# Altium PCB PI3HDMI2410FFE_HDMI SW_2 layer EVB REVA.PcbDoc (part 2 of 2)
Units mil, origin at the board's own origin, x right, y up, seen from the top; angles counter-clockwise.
Board outline 4919 x 3441 mil, 2 copper layers (Top Layer, Bottom Layer); 75 components, 82 nets, 1371 pads, 135 vias.
Unrouted connection lines stored in the file: 1.
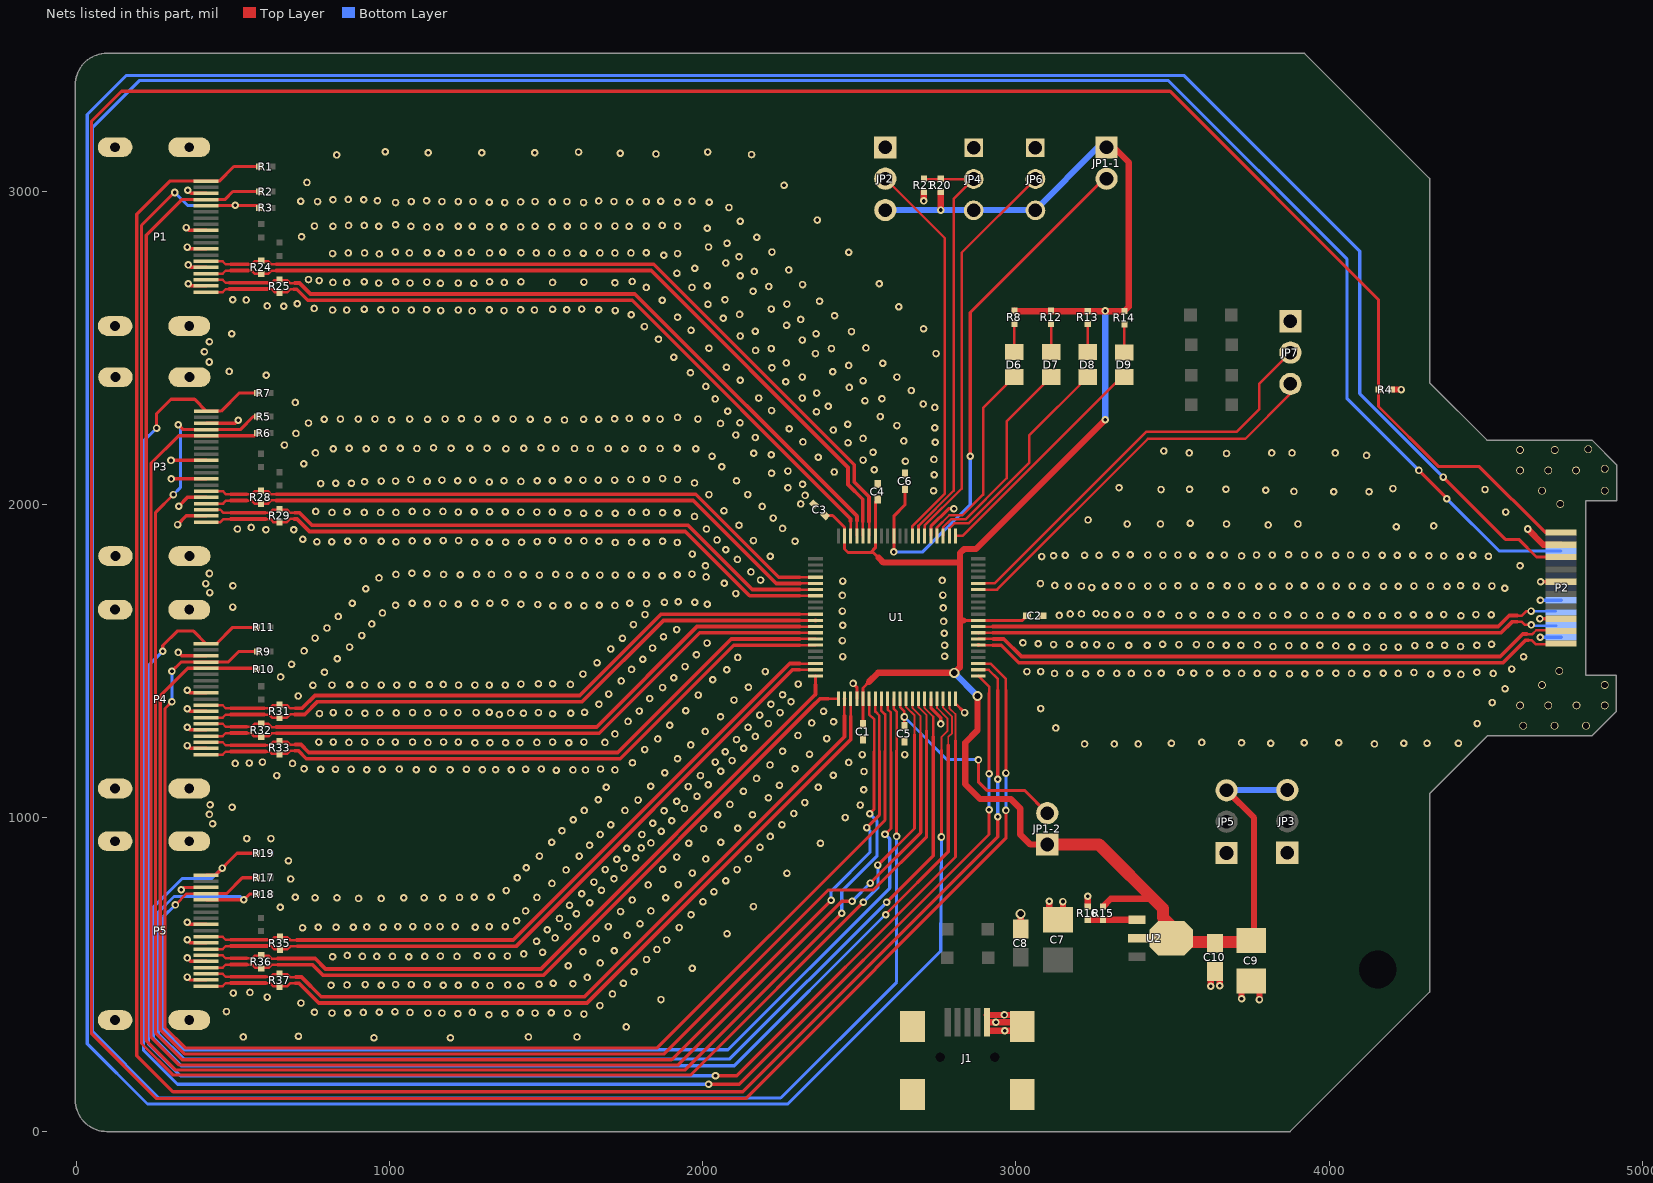
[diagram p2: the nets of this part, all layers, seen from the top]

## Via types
v1: diameter 24, hole 12, Top Layer to Bottom Layer, tented both sides, 131 vias
v2: diameter 32, hole 20, Top Layer to Bottom Layer, tented both sides, 4 vias

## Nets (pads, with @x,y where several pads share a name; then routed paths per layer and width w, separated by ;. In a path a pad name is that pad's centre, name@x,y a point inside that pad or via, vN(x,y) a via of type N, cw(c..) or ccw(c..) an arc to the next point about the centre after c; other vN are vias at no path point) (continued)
D1C+: P4.7 R31.2 U1.11 | length 2081.3
  Top Layer w8: P4.7@415.06,1320.11 468.32,1320.11 478,1329.8 495,1329.8 ; 600,1329.8 616.2,1329.8 625.68,1320.32 673.32,1320.32 683,1330 699,1330 ; 2309.65,1630 U1.11@2360,1630
  Top Layer w12: 495,1329.8 600,1329.8 ; 699,1330 730,1330 771,1371 1616,1371 1875,1630 2309.65,1630 ; U1.11@2360,1630.16 U1.11@2360.16,1630.16
D1C-: P4.9 R31.1 U1.10 | length 2081.5
  Top Layer w8: P4.9@415.06,1359.48 468.32,1359.48 478,1349.8 495,1349.8 ; 600,1349.8 618.8,1349.8 628.68,1359.68 673.32,1359.68 683,1350 700,1350 ; 2309.65,1650 2321.38,1650 2321.54,1649.84 U1.10@2360.16,1649.84
  Top Layer w12: 495,1349.8 600,1349.8 ; 700,1350 721.72,1350 762.72,1391 1607.72,1391 1866.72,1650 2309.65,1650
D1D+: P5.7 R35.2 U1.19 | length 2323.1
  Top Layer w8: P5.7@415.06,581.11 468.32,581.11 478,590.8 495,590.8 ; 610,590.8 622.2,590.8 632.68,580.32 674.32,580.32 684,590 706,590 ; 2310,1472.52 2310.16,1472.68 U1.19@2360.16,1472.68
  Top Layer w12: 495,590.8 610,590.8 ; 706,590 1404,590 2286.52,1472.52 2310,1472.52
D1D-: P5.9 R35.1 U1.18 | length 2322.4
  Top Layer w8: P5.9@415.06,620.48 468.32,620.48 478,610.8 495,610.8 ; 610,610.8 624.8,610.8 633.68,619.68 674.32,619.68 684,610 705,610 ; 2310,1492.52 2321.38,1492.52 2321.54,1492.36 U1.18@2360.16,1492.36
  Top Layer w12: 495,610.8 610,610.8 ; 705,610 1395.72,610 2278.24,1492.52 2310,1492.52
D2+: P2.4 U1.48 | length 1863.9
  Top Layer w8: U1.48@2880,1590.63 2927,1590.63 ; 4600,1625.63 4615,1625.63 4624.69,1615.94 v1(4644.69,1615.94)
  Top Layer w12: U1.48@2879.84,1590.79 U1.48@2880,1590.79 ; 2927,1590.63 4547.63,1590.63 4582.63,1625.63 4600,1625.63
  Bottom Layer w8: v1(4644.69,1615.94) 4647.63,1613 P2.4@4724,1613
D2-: P2.6 U1.49 | length 1862.7
  Top Layer w8: U1.49@2879.84,1610.47 2918.46,1610.47 2918.62,1610.63 2926,1610.63 ; 4600,1645.63 4615,1645.63 4629.37,1660 v1(4644,1660)
  Top Layer w12: 2926,1610.63 4539.35,1610.63 4574.35,1645.63 4600,1645.63
  Bottom Layer w8: v1(4644,1660) P2.6@4722,1660
D2A+: P1.4 R24.2 U1.76 | length 2559.8
  Top Layer w8: P1.4@415.06,2737.06 468.32,2737.06 478,2746.74 495,2746.74 ; 550,2746.74 560.26,2746.74 569.68,2737.32 614.32,2737.32 624,2747 640,2747 ; 2511.02,1946 2511.73,1945.29 U1.76@2511.73,1899.84
  Top Layer w12: 495,2746.74 550,2746.74 ; 640,2747 1835.72,2747 2464,2118.72 2464,2063.72 2511.02,2016.69 2511.02,1946
D2A-: P1.6 R24.1 U1.75 | length 2592.8
  Top Layer w8: P1.6@415.06,2776.43 468.32,2776.43 478,2766.74 495,2766.74 ; 550,2766.74 559.74,2766.74 569.68,2776.68 614.32,2776.68 624,2767 640,2767 ; U1.75@2531.02,1899.84 2531.02,1946
  Top Layer w12: 495,2766.74 550,2766.74 ; 640,2767 1844,2767 2484,2127 2484,2072 2531.02,2024.98 2531.02,1946
D2B+: P3.4 R28.2 U1.5 | length 2065.8
  Top Layer w8: P3.4@416.06,2003.06 469.32,2003.06 479,2012.74 495,2012.74 ; 545,2012.74 560.57,2012.74 570,2003.32 613.32,2003.32 623,2013 640,2013 ; 2311,1748.11 2321.38,1748.11 2321.54,1748.27 U1.5@2360.16,1748.27
  Top Layer w12: 495,2012.74 545,2012.74 ; 640,2013 1969.72,2013 2234.61,1748.11 2311,1748.11
D2B-: P3.6 R28.1 U1.4 | length 2066
  Top Layer w8: P3.6@416.06,2042.43 469.32,2042.43 479,2032.74 495,2032.74 ; 545,2032.74 561.74,2032.74 571.68,2042.68 613.32,2042.68 623,2033 640,2033 ; 2310,1768.11 2360,1768.11 U1.4@2360.16,1767.95
  Top Layer w12: 495,2032.74 545,2032.74 ; 640,2033 1978,2033 2242.89,1768.11 2310,1768.11
D2C+: P4.4 R32.2 U1.13 | length 2090.3
  Top Layer w8: P4.4@415.06,1261.06 468.32,1261.06 478,1270.74 495,1270.74 ; 545,1270.74 558.26,1270.74 568.68,1260.32 614.32,1260.32 624,1270 640,1270 ; 2310,1590.63 2360,1590.63 U1.13@2360.16,1590.79
  Top Layer w12: 495,1270.74 545,1270.74 ; 640,1270 1670,1270 1990.63,1590.63 2310,1590.63
D2C-: P4.6 R32.1 U1.12 | length 2089.7
  Top Layer w8: P4.6@415.06,1300.43 468.32,1300.43 478,1290.74 495,1290.74 ; 544,1290.74 560.74,1290.74 569.68,1299.68 614.32,1299.68 624,1290 640,1290 ; 2310,1610.63 2321.38,1610.63 2321.54,1610.47 U1.12@2360.16,1610.47
  Top Layer w12: 495,1290.74 544,1290.74 ; 640,1290 1661.72,1290 1982.35,1610.63 2310,1610.63
D2D+: P5.4 R36.2 U1.21 | length 2409.3
  Top Layer w8: P5.4@415.06,522.06 468.32,522.06 478,531.74 495,531.74 ; 545,531.74 562.26,531.74 572.68,521.32 614.32,521.32 624,531 645,531 ; 2400,1380.16 U1.21@2432.99,1380.16
  Top Layer w12: 495,531.74 545,531.74 ; 645,531 755,531 788,498 1492,498 2360.62,1366.62 2360.76,1366.62 2374.3,1380.16 2400,1380.16
D2D-: P5.6 R36.1 U1.20 | length 2392.2
  Top Layer w8: P5.6@415.06,561.43 468.32,561.43 478,551.74 495,551.74 ; 544,551.74 561.74,551.74 570.68,560.68 614.32,560.68 624,551 645,551 ; 2360.16,1425 U1.20@2360.16,1452.99
  Top Layer w12: 495,551.74 544,551.74 ; 645,551 763.28,551 796.28,518 1483.72,518 2352.34,1386.62 2352.48,1386.62 2360.16,1394.3 2360.16,1425
D3+: P2.1 U1.46 | length 1894.3
  Top Layer w8: U1.46@2880,1551.26 2926,1551.26 ; 4634,1566.57 4646.57,1566.57 4659.15,1554 P2.1@4716,1554
  Top Layer w12: U1.46@2879.84,1551.42 U1.46@2880,1551.42 ; 2926,1551.26 2952.74,1551.26 3009,1495 4554,1495 4625.57,1566.57 4634,1566.57
D3-: P2.3 U1.47 | length 1893.3
  Top Layer w8: U1.47@2879.84,1571.1 2918.46,1571.1 2918.62,1571.26 2928,1571.26 ; 4630,1586.57 4648,1586.57 4660.43,1599 P2.3@4715,1599
  Top Layer w12: 2928,1571.26 2961.02,1571.26 3017.28,1515 4545.72,1515 4617.29,1586.57 4630,1586.57
D3A+: P1.1 R25.2 U1.78 | length 2427.8
  Top Layer w8: P1.1@415.06,2678 468.32,2678 478,2687.68 489,2687.68 ; 615,2687.68 625.32,2687.68 635.68,2677.32 673.32,2677.32 683,2687 695,2687 ; 2472.2,1947 2472.2,1938.62 2472.36,1938.46 U1.78@2472.36,1899.84
  Top Layer w12: 489,2687.68 615,2687.68 ; 695,2687 704.72,2687 739.72,2652 1775,2652 2472.2,1954.8 2472.2,1947
D3A-: P1.3 R25.1 U1.77 | length 2460.3
  Top Layer w8: P1.3@415.06,2717.37 468.32,2717.37 478,2707.69 490,2707.69 ; 615,2707.69 624.69,2707.69 633.68,2716.68 673.32,2716.68 683,2707 698,2707 ; U1.77@2492.05,1899.84 2492.2,1900 2492.2,1948
  Top Layer w12: 490,2707.69 615,2707.69 ; 698,2707 713,2707 748,2672 1783.28,2672 2492.2,1963.08 2492.2,1948
D3B+: P3.1 R29.2 U1.7 | length 2057.7
  Top Layer w8: P3.1@416.06,1944 461,1944 470.68,1953.68 495,1953.68 ; 605,1953.68 620.63,1953.68 630,1944.32 673.32,1944.32 683,1954 697,1954 ; 2310,1708.74 2321.38,1708.74 2321.54,1708.9 U1.7@2360.16,1708.9
  Top Layer w12: 495,1953.68 605,1953.68 ; 697,1954 705,1954 745,1914 1944.72,1914 2149.98,1708.74 2310,1708.74
D3B-: P3.3 R29.1 U1.6 | length 2057.9
  Top Layer w8: P3.3@416.06,1983.37 461,1983.37 470.68,1973.69 495,1973.69 ; 604,1973.69 618.69,1973.69 628.68,1983.68 673.32,1983.68 683,1974 699,1974 ; 2310,1728.74 2360,1728.74 U1.6@2360.16,1728.58
  Top Layer w12: 495,1973.69 604,1973.69 ; 699,1974 713.28,1974 753.28,1934 1953,1934 2158.26,1728.74 2310,1728.74
D3C+: P4.1 R33.2 U1.15 | length 2116.6
  Top Layer w8: P4.1@415.06,1202 468.32,1202 478,1211.68 495,1211.68 ; 605,1211.68 618.32,1211.68 625.68,1204.32 673.32,1204.32 683,1214 699,1214 ; 2310,1551.26 2360,1551.26 U1.15@2360.16,1551.42
  Top Layer w12: 495,1211.68 605,1211.68 ; 699,1214 709.72,1214 734.72,1189 1737,1189 2099.26,1551.26 2310,1551.26
D3C-: P4.3 R33.1 U1.14 | length 2118.6
  Top Layer w8: P4.3@415.06,1241.37 468.32,1241.37 478,1231.69 495,1231.69 ; 603,1231.69 617.69,1231.69 629.68,1243.68 673.32,1243.68 683,1234 700,1234 ; 2309,1571.26 2321.38,1571.26 2321.54,1571.1 U1.14@2360.16,1571.1
  Top Layer w12: 495,1231.69 603,1231.69 ; 700,1234 718,1234 743,1209 1728.72,1209 2090.98,1571.26 2309,1571.26
D3D+: P5.1 R37.2 U1.23 | length 2574.1
  Top Layer w8: P5.1@415.06,463 468.32,463 478,472.68 495,472.68 ; 605,472.68 619.32,472.68 629.68,462.32 673.32,462.32 683,472 700,472 ; 2472.36,1323.53 U1.23@2472.36,1380.16
  Top Layer w12: 495,472.68 605,472.68 ; 700,472 711.72,472 774.72,409 1631,409 2472.52,1250.52 2472.52,1323.53
D3D-: P5.3 R37.1 U1.22 | length 2540.4
  Top Layer w8: P5.3@415.06,502.37 468.32,502.37 478,492.69 495,492.69 ; 605,492.69 620.69,492.69 629.68,501.68 673.32,501.68 683,492 701,492 ; 2452.52,1326.33 U1.22@2452.52,1380
  Top Layer w12: 495,492.69 605,492.69 ; 701,492 720,492 783,429 1622.72,429 2452.52,1258.8 2452.52,1326.33 ; U1.22@2452.68,1380 U1.22@2452.68,1380.16
GND: C1.2 C2.2 C3.2 C4.2 C5.2 C6.2 C7.2 C8.1 C9.2 C10.1 J1.5 JP2.1 JP3.1 JP4.1 JP5.1 JP6.1 JP7.1 P1.2 P1.5 P1.8 P1.11 P1.17 P1.20 P1.21 P1.22 P1.23 P2.2 P2.5 P2.8 P2.11 P2.17 P2.20 P3.2 P3.5 P3.8 P3.11 P3.17 P3.20 P3.21 P3.22 P3.23 P4.2 P4.5 P4.8 P4.11 P4.17 P4.20 P4.21 P4.22 P4.23 P5.2 P5.5 P5.8 P5.11 P5.17 P5.20 P5.21 P5.22 P5.23 pad.6 pad.7 pad.9 pad.10 pad.11 pad.12 pad.13 pad.14 pad.15 pad.16 pad.17 pad.18 pad.19 pad.20 pad.21 pad.22 pad.23 pad.24 pad.25 pad.26 pad.27 pad.28 pad.29 pad.30 pad.31 pad.32 pad.33 pad.34 pad.35 pad.36 pad.37 pad.38 pad.39 pad.40 pad.41 pad.42 pad.43 pad.44 pad.45 pad.46 pad.47 pad.48 pad.49 pad.50 pad.51 pad.52 pad.53 pad.54 pad.55 pad.56 pad.57 pad.58 pad.59 pad.60 pad.61 pad.62 pad.63 pad.64 pad.65 pad.66 pad.67 pad.68 pad.69 pad.70 pad.71 pad.72 pad.73 pad.74 pad.75 pad.76 pad.77 pad.78 pad.79 pad.80 pad.81 pad.82 pad.83 pad.84 pad.85 pad.86 pad.87 pad.88 pad.89 pad.90 pad.91 pad.92 pad.93 pad.94 pad.95 pad.96 pad.97 pad.98 pad.99 pad.100 pad.101 pad.102 pad.103 pad.104 pad.105 pad.106 pad.107 pad.108 pad.109 pad.110 pad.111 pad.112 pad.113 pad.114 pad.115 pad.116 pad.117 pad.118 pad.119 pad.120 pad.121 pad.122 pad.123 pad.124 pad.125 pad.126 pad.127 pad.128 pad.129 pad.132 pad.133 pad.134 pad.135 pad.136 pad.137 pad.138 pad.139 pad.140 pad.141 pad.142 pad.144 pad.145 pad.146 pad.147 pad.149 pad.150 pad.151 pad.152 pad.153 pad.154 pad.155 pad.156 pad.157 pad.158 pad.159 pad.160 pad.161 pad.162 pad.163 pad.164 pad.165 pad.166 pad.167 pad.168 pad.169 pad.170 pad.171 pad.172 pad.173 pad.174 pad.175 pad.176 pad.177 pad.178 pad.179 pad.180 pad.181 pad.182 pad.183 pad.184 pad.185 pad.186 pad.187 pad.188 pad.189 pad.190 pad.191 pad.192 pad.193 pad.194 pad.195 pad.196 pad.197 pad.198 pad.199 pad.200 pad.201 pad.202 pad.203 pad.204 pad.205 pad.206 pad.207 pad.208 pad.209 pad.210 pad.211 pad.212 pad.213 pad.214 pad.215 pad.216 pad.217 pad.218 pad.219 pad.220 pad.221 pad.222 pad.223 pad.224 pad.225 pad.226 pad.227 pad.228 pad.229 pad.230 pad.231 pad.232 pad.233 pad.234 pad.235 pad.236 pad.237 pad.238 pad.239 pad.240 pad.241 pad.242 pad.243 pad.244 pad.245 pad.246 pad.247 pad.248 pad.249 pad.250 pad.251 pad.252 pad.253 pad.254 pad.255 pad.256 pad.257 pad.258 pad.259 pad.260 pad.261 pad.262 pad.263 pad.264 pad.265 pad.266 pad.267 pad.268 pad.269 pad.270 pad.271 pad.272 pad.273 pad.274 pad.275 pad.276 pad.277 pad.278 pad.279 pad.280 pad.281 pad.282 pad.283 pad.284 pad.285 pad.286 pad.287 pad.288 pad.289 pad.290 pad.291 pad.292 pad.293 pad.294 pad.295 pad.296 pad.297 pad.298 pad.299 pad.300 pad.301 pad.302 pad.303 pad.304 pad.305 pad.306 pad.307 pad.308 pad.309 pad.310 pad.311 pad.312 pad.313 pad.314 pad.315 pad.316 pad.317 pad.318 pad.319 pad.320 pad.321 pad.322 pad.323 pad.324 pad.325 pad.326 pad.327 pad.328 pad.329 pad.330 pad.331 pad.332 pad.333 pad.334 pad.335 pad.336 pad.337 pad.338 pad.339 pad.340 pad.341 pad.342 pad.343 pad.344 pad.345 pad.346 pad.347 pad.348 pad.349 pad.350 pad.351 pad.352 pad.353 pad.354 pad.355 pad.356 pad.357 pad.358 pad.359 pad.360 pad.361 pad.362 pad.363 pad.364 pad.365 pad.366 pad.367 pad.368 pad.369 pad.370 pad.371 pad.372 pad.373 pad.374 pad.375 pad.376 pad.377 pad.378 pad.379 pad.380 pad.381 pad.382 pad.383 pad.384 pad.385 pad.386 pad.387 pad.388 pad.389 pad.390 pad.391 pad.392 pad.393 pad.394 pad.395 pad.396 pad.397 pad.398 pad.399 pad.400 pad.401 pad.402 pad.403 pad.404 pad.405 pad.406 pad.407 pad.408 pad.409 pad.410 pad.411 pad.412 pad.413 pad.414 pad.415 pad.416 pad.417 pad.418 pad.419 pad.420 pad.421 pad.422 pad.423 pad.424 pad.425 pad.426 pad.427 pad.428 pad.429 pad.430 pad.431 pad.432 pad.433 pad.434 pad.435 pad.436 pad.437 pad.438 pad.439 pad.440 pad.441 pad.442 pad.443 pad.444 pad.445 pad.446 pad.447 pad.448 pad.449 pad.450 pad.451 pad.452 pad.453 pad.454 pad.455 pad.456 pad.457 pad.458 pad.459 pad.460 pad.461 pad.462 pad.463 pad.464 pad.465 pad.466 pad.467 pad.468 pad.469 pad.470 pad.471 pad.472 pad.473 pad.474 pad.475 pad.476 pad.477 pad.478 pad.479 pad.480 pad.481 pad.482 pad.483 pad.484 pad.485 pad.486 pad.487 pad.488 pad.489 pad.490 pad.491 pad.492 pad.493 pad.494 pad.495 pad.496 pad.497 pad.498 pad.499 pad.500 pad.501 pad.516 pad.550 pad.566 pad.571 pad.577 pad.592 pad.593 pad.594 pad.595 pad.596 pad.597 pad.598 pad.599 pad.600 pad.601 pad.602 pad.603 pad.604 pad.605 pad.606 pad.607 pad.608 pad.610 pad.611 pad.612 pad.613 pad.614 pad.615 pad.616 pad.617 pad.618 pad.619 pad.620 pad.621 pad.622 pad.623 pad.624 pad.629 pad.630 pad.631 pad.632 pad.633 pad.634 pad.635 pad.636 pad.637 pad.638 pad.639 pad.640 pad.641 pad.642 pad.643 pad.644 pad.645 pad.646 pad.647 pad.648 pad.649 pad.650 pad.651 pad.652 pad.653 pad.654 pad.655 pad.656 pad.657 pad.658 pad.659 pad.660 pad.661 pad.662 pad.663 pad.664 pad.665 pad.666 pad.667 pad.668 pad.669 pad.670 pad.671 pad.672 pad.673 pad.674 pad.675 pad.676 pad.677 pad.678 pad.679 pad.680 pad.681 pad.682 pad.683 pad.684 pad.685 pad.686 pad.687 pad.688 pad.689 pad.690 pad.691 pad.692 pad.693 pad.694 pad.695 pad.696 pad.697 pad.698 pad.699 pad.700 pad.701 pad.702 pad.703 pad.704 pad.705 pad.706 pad.707 pad.708 pad.709 pad.710 pad.711 pad.712 pad.713 pad.714 pad.715 pad.716 pad.717 pad.718 pad.719 pad.720 pad.721 pad.722 pad.723 pad.724 pad.725 pad.726 pad.727 pad.728 pad.729 pad.730 pad.731 pad.732 pad.733 pad.734 pad.735 pad.736 pad.737 pad.738 pad.739 pad.740 pad.741 pad.742 pad.743 pad.744 pad.745 pad.746 pad.747 pad.748 pad.749 pad.750 pad.751 pad.752 pad.753 pad.754 pad.755 pad.756 pad.757 pad.758 pad.759 pad.760 pad.761 pad.762 pad.763 pad.764 pad.765 pad.766 pad.767 pad.768 pad.769 pad.770 pad.771 pad.772 pad.773 pad.774 pad.775 pad.776 pad.777 pad.778 pad.779 pad.780 pad.781 pad.782 pad.783 pad.784 pad.785 pad.786 pad.787 pad.788 pad.789 pad.790 pad.791 pad.792 pad.793 pad.794 pad.795 pad.796 pad.797 pad.798 pad.799 pad.800 pad.801 pad.802 pad.803 pad.804 pad.805 pad.806 pad.807 pad.808 pad.809 pad.810 pad.811 pad.812 pad.813 pad.814 pad.815 pad.816 pad.817 pad.818 pad.819 pad.820 pad.823 pad.824 pad.825 pad.826 pad.827 pad.828 pad.829 pad.830 pad.831 pad.832 pad.833 pad.834 pad.835 pad.836 pad.837 pad.838 pad.839 pad.840 pad.841 pad.842 pad.843 pad.844 pad.845 pad.846 pad.847 pad.848 pad.849 pad.850 pad.851 pad.852 pad.853 pad.854 pad.856 pad.857 pad.858 pad.859 pad.860 pad.861 pad.862 pad.863 pad.864 pad.865 pad.866 pad.867 pad.868 pad.869 pad.870 pad.871 pad.872 pad.873 pad.874 pad.875 pad.876 pad.877 pad.878 pad.879 pad.880 pad.881 pad.882 pad.883 pad.884 pad.885 pad.886 pad.887 pad.888 pad.889 pad.890 pad.891 pad.892 pad.893 pad.894 pad.895 pad.896 pad.897 pad.898 pad.899 pad.900 pad.901 pad.902 pad.903 pad.904 pad.905 pad.906 pad.907 pad.908 pad.909 pad.910 pad.911 pad.912 pad.913 pad.914 pad.915 pad.916 pad.917 pad.918 pad.919 pad.920 pad.921 pad.922 pad.923 pad.924 pad.925 pad.926 pad.927 pad.928 pad.929 pad.930 pad.931 pad.932 pad.933 pad.934 pad.935 pad.936 pad.937 pad.938 pad.939 pad.940 pad.941 pad.942 pad.943 pad.944 pad.945 pad.946 pad.947 pad.948 pad.949 pad.950 pad.951 pad.952 pad.953 pad.954 pad.955 pad.956 pad.957 pad.958 pad.959 pad.960 pad.961 pad.962 pad.963 pad.964 pad.965 pad.966 pad.967 pad.968 pad.969 pad.970 pad.971 pad.972 pad.973 pad.974 pad.975 pad.976 pad.977 pad.978 pad.979 pad.980 pad.981 pad.982 pad.983 pad.984 pad.985 pad.986 pad.987 pad.988 pad.989 pad.990 pad.991 pad.992 pad.993 pad.994 pad.995 pad.996 pad.997 pad.998 pad.999 pad.1000 pad.1001 pad.1002 pad.1003 pad.1006 pad.1007 pad.1008 pad.1009 pad.1010 pad.1011 pad.1012 pad.1013 pad.1014 pad.1015 pad.1016 pad.1017 pad.1018 pad.1019 pad.1020 pad.1021 pad.1022 pad.1023 pad.1024 pad.1025 pad.1026 pad.1027 pad.1028 pad.1029 pad.1030 pad.1031 pad.1032 pad.1033 pad.1034 pad.1035 pad.1036 pad.1037 pad.1038 pad.1039 pad.1041 pad.1042 pad.1043 pad.1044 pad.1046 pad.1047 pad.1048 pad.1049 pad.1050 pad.1051 pad.1052 pad.1053 pad.1054 pad.1055 pad.1056 pad.1057 pad.1058 pad.1059 pad.1060 pad.1062 pad.1063 pad.1065 pad.1066 pad.1069 pad.1070 pad.1072 pad.1074 pad.1076 pad.1079 pad.1082 pad.1085 pad.1088 pad.1090 pad.1092 pad.1094 pad.1097 pad.1098 pad.1099 pad.1101 pad.1104 pad.1107 pad.1110 pad.1112 pad.1115 pad.1117 pad.1119 pad.1121 pad.1123 pad.1125 pad.1127 pad.1129 pad.1131 pad.1132 pad.1133 pad.1134 pad.1135 pad.1136 pad.1137 R4.1 R16.2 R21.2 U1.24 U1.36 U1.40 U1.65 | length 2877.3
  Top Layer w10: v1(336,771) 342.96,777.96 P5.17@415.06,777.96 ; v1(2480,1429) 2492.05,1416.95 U1.24@2492.05,1380.16 ; U1.36@2728.27,1380.16 2728.27,1351.73 2760,1320 v1(2760,1300) ; U1.65@2728.27,1899.84 2728.27,1930.27 2785,1987 v1(2802,1987) ; U1.40@2807.01,1380.16 2807.01,1364.99 v1(2836,1336)
  Top Layer w11: v1(303.15,2140.85) P3.11@416.06,2140.85 ; v1(304.2,2081.8) P3.8@416.06,2081.8 ; v1(324,1936) 351.68,1963.68 P3.2@416.06,1963.68 ; v1(326,1528) 337.04,1516.96 P4.17@415.06,1516.96 ; v1(328,1995) 355.74,2022.74 P3.5@416.06,2022.74 ; v1(352,2884) 361.15,2874.85 P1.11@415.06,2874.85 ; v1(355,492) 364.32,482.68 P5.2@415.06,482.68 ; v1(355,553) 366.26,541.74 P5.5@415.06,541.74 ; v1(355,611) 365.2,600.8 P5.8@415.06,600.8 ; v1(355,667) 362.15,659.85 P5.11@415.06,659.85 ; v1(355,1231) 364.32,1221.68 P4.2@415.06,1221.68 ; v1(355,1289) 363.26,1280.74 P4.5@415.06,1280.74 ; v1(355,1348) 363.2,1339.8 P4.8@415.06,1339.8 ; v1(355,1407) 363.15,1398.85 P4.11@415.06,1398.85 ; v1(355,2822) 361.2,2815.8 P1.8@415.06,2815.8 ; v1(357,3003) 367.04,2992.96 P1.17@415.06,2992.96 ; v1(358,2705) 365.32,2697.68 P1.2@415.06,2697.68 ; v1(358,2765) 366.26,2756.74 P1.5@415.06,2756.74 ; P3.17@416.06,2258.96 507.96,2258.96 v1(518,2269)
  Top Layer w12: v1(4672.37,1635.63) P2.5@4739.63,1635.63 ; v1(4674.26,1753.74) P2.11@4739.63,1753.74
  Top Layer w20: v1(2706,2969) R21.2@2706,2998 ; J1.5@2907,371 J1.5@2998,371 ; J1.5@2908,321 J1.5@2999,321 ; J1.5@2907.99,347.9 J1.5@2991.1,347.9 ; C8.1@3015,645 v2(3015,694) ; C7.2@3106,691 v1(3106,734) ; C7.2@3150,683 v1(3150,733) ; R16.2@3229.03,717.27 v1(3229.03,749.97) ; v1(3622,463) C10.1@3622,495 ; v1(3650,464) C10.1@3650,493 ; v1(3720,423) C9.2@3720,454 ; v1(3777,420) C9.2@3777,450 ; R4.1@4199.95,2367.03 v1(4229.97,2367.03) ; v1(4633,1922) 4683.15,1871.85 P2.17@4739.63,1871.85
  Bottom Layer w12: v1@4672.32,1694.68 P2.8@4739.63,1694.68 ; v1(4673.57,1576.57) P2.2@4739.63,1576.57
  other v1: 2964,321 2936,347.9 2963,371 436,981 426,1011 498,1034 428,1042 2509,1202 2645,1202 2447,1515 2772,1516 2772,1551 2446,1566 2771,1589 2447,1615 2769,1627 3138,1646 2446,1660 2768,1670 500,1673 4674,1695 2446,1710 2767,1711 427,1719 501,1741 414,1748 2447,1756 2765,1758 426,1780 2327,2029 2548,2111 2647,2138 425,2455 410,2488 426,2520
HPD_A: P1.19 R1.1 U1.42 | length 6849.2
  Top Layer w8: U1.42@2879.84,1472.68 2912.32,1472.68 2942,1443 2942,1408
  Top Layer w10: R1.1@584.05,3078.97 503.97,3078.97 457.33,3032.33 299.33,3032.33 194,2927 194,241 309,126 2128,126 2942,940 v1(2942,1004) ; v1(2942,1123) 2942,1408
  Bottom Layer w10: v1(2942,1004) v1(2942,1123)
HPD_B: P3.19 R7.1 U1.41 | length 6022.4
  Top Layer w8: U1.41@2879.84,1452.99 2914,1418.83 2914,1399
  Top Layer w10: v1(257,2244) 257,2290 303,2336 378.39,2336 P3.19@416.06,2298.33 463.33,2298.33 520.94,2355.94 R7.1@578.09,2355.94 ; v1(2019,150) 2117,150 2914,947 v1(2914,1026) ; v1(2914,1141) 2914,1399
  Bottom Layer w10: v1(257,2244) 215,2202 215,259 324,150 v1(2019,150) ; v1(2914,1026) v1(2914,1141)
HPD_C: P4.19 R11.1 U1.39 | length 5068.7
  Top Layer w6: U1.39@2787.32,1380.16 2787.32,1350.68 2807,1331 2807,1247
  Top Layer w10: v1(277,1532) 277,1550 323,1596 375.39,1596 P4.19@415.06,1556.33 448.33,1556.33 499.94,1607.94 R11.1@578.09,1607.94 ; v1(2041,177) 2109,177 2807,875 2807,1247
  Bottom Layer w10: v1(277,1532) 231,1486 231,279 333,177 v1(2041,177)
HPD_D: P5.19 R19.1 U1.38 | length 4241.9
  Top Layer w6: U1.38@2767.64,1380.16 2767.64,1351.36 2796,1323 2796,1270.5 2784,1258.5 2784,1233
  Top Layer w10: P5.19@415.06,817.33 444.33,817.33 513.94,886.94 R19.1@578.09,886.94 ; v1@2583.5,691.5 2784,892 2784,1233
  Bottom Layer w10: v1(466.72,839.72) 433.5,806.5 338.5,806.5 247,715 247,298 336,209 2101,209 v1@2583.5,691.5
  other v1: 2584,691
HPD_SINK: P2.19 R4.2 U1.43 | length 12386.6
  Top Layer w8: U1.43@2879.84,1492.36 2918.64,1492.36 2968,1443 2968,1408
  Top Layer w10: 2966,933 2137,104 257,104 50,311 50,3224 145,3319 3492,3319 4157,2654 4157,2313 4349,2121 4479,2121 4688.78,1911.22 P2.19@4739.63,1911.22 ; 2968,935 v1(2968,1024) ; v1(2968,1143) 2968,1408
  Bottom Layer w10: v1(2968,1024) v1(2968,1143)
NetD6_1: D6.1 R8.1 | length 89.6
  Top Layer w8: D6.1@2994,2486.37 R8.1@2994,2576.02
NetD6_2: D6.2 U1.64 | length 634.5
  Top Layer w8: U1.64@2747.56,1899.84 2747.56,1926.56 2787,1966 2829,1966 2895,2032 2895,2308.63 D6.2@2994,2407.63
NetD7_1: D7.1 R12.1 | length 90.6
  Top Layer w8: D7.1@3112,2486.37 R12.1@3112.03,2577.05
NetD7_2: D7.2 U1.63 | length 677.4
  Top Layer w8: U1.63@2767.64,1899.84 2767.64,1927.64 2793,1953 2839,1953 2970,2084 2970,2265.63 D7.2@3112,2407.63
NetD8_1: D8.1 R13.1 | length 89.6
  Top Layer w8: D8.1@3229,2486.37 R13.1@3229.03,2576.05
NetD8_2: D8.2 U1.62 | length 717.7
  Top Layer w8: U1.62@2787.32,1899.84 2787.32,1924.32 2803,1940 2849,1940 3043,2134 3043,2221.63 D8.2@3229,2407.63
NetD9_1: D9.1 R14.1 | length 88.6
  Top Layer w8: D9.1@3345,2485.37 R14.1@3345,2574.02
NetD9_2: D9.2 U1.61 | length 747.9
  Top Layer w8: U1.61@2807.01,1899.84 2829.84,1899.84 3336.63,2406.63 D9.2@3345,2406.63
NetR15_1: R15.1 R16.1 U2.1 | length 156.4
  Top Layer w20: R16.1@3230.02,675.06 U2.1@3386.37,675.06
OE#: JP2.2 U1.68 | length 1261.8
  Top Layer w8: JP2.2@2583,3040 2773,2850 2773,2035 2669.21,1931.21 U1.68@2669.21,1899.84
SCL_A: P1.15 R3.2 U1.32 | length 6453.6
  Top Layer w6.5: U1.32@2649.53,1380.16 2649.53,1353.47 2676,1327 2676,1266
  Top Layer w10: v1@314,2996 209,2891 209,280 310,179 1961,179 v1(2513,731) ; P1.15@406,2955 576.76,2955 R3.2@584.73,2947.03 ; v1(2559.21,849.34) 2676,966.12 2676,1266
  Bottom Layer w10: v1(315,2996) 356,2955 v1(508,2955) ; v1(2513,731) 2559.21,777.21 v1(2559.21,849.34)
SCL_B: P3.15 R6.2 U1.33 | length 5448.3
  Top Layer w6.5: U1.33@2669.21,1380.16 2669.21,1351.79 2696,1325 2696,1267
  Top Layer w10: R6.2@577.78,2228 569.37,2219.59 327.59,2219.59 239,2131 239,302 330,211 1921,211 2444,734 v1(2477,734) ; v1(2535,792) 2696,953 2696,1267
  Bottom Layer w10: v1(2477,734) v1(2535,792)
SCL_C: P4.15 R10.2 U1.34 | length 4624.2
  Top Layer w6.5: U1.34@2689.29,1380.16 2689.29,1352.71 2715,1327 2715,1279
  Top Layer w10: R10.2@575.19,1477.59 356.59,1477.59 269,1390 269,324 346,247 1878,247 2401,770 2545,770 2715,940 2715,1279
SCL_CTL: JP7.3 U1.55 | length 1286.2
  Top Layer w8: U1.55@2879.84,1728.58 2939.58,1728.58 3421,2210 3732,2210 3876,2354 JP7.3@3876,2385
SCL_D: P5.15 R18.2 U1.35 | length 4182.3
  Top Layer w6.5: U1.35@2708.58,1380.16 2708.58,1350.42 2736,1323 2736,1260
  Top Layer w8: 2736,1220 2736,1260
  Top Layer w10: P5.15@415.06,738.59 v1(535.59,738.59) 554,757 R18.2@577.78,757 ; v1@2587.5,730.5 2736,879 2736,1260
  Bottom Layer w10: v1(535.59,738.59) 525.18,749 312.75,749 263,699.25 263,312 344,231 2087,231 v1(2587,731)
SCL_SINK: P2.15 U1.37 | length 12457.2
  Top Layer w6: U1.37@2747.95,1380.16 2747.95,1351.05 2781,1318 2781,1277 2762,1258 2762,1217
  Top Layer w10: v1(2762,939) 2762,1217 ; v1(4364.07,2087.7) 4562.07,1889 4605,1889 4661.52,1832.48 P2.15@4739.63,1832.48
  Bottom Layer w10: v1(2762,939) 2760,575 2272,87 228,87 36,279 36,3245 161,3370 3536,3370 4097,2809 4097,2354 v1(4364.07,2087.7)
SDA_A: P1.16 R2.2 U1.26 | length 6208.9
  Top Layer w8: U1.26@2531.42,1380.16 2531.42,1330.58 2547,1315 2547,1211
  Top Layer w10: R2.2@584.73,2999.03 500.76,2999.03 475,2973.28 337.28,2973.28 224,2860 224,289 318,195 1943,195 v1(2444,696) ; v1(2533,1013) 2547,1027 2547,1211
  Bottom Layer w10: v1(2444,696) 2444,766 2557,879 2557,989 v1(2533,1013)
SDA_B: P3.16 R5.2 U1.27 | length 5375.8
  Top Layer w8: U1.27@2551.1,1380.16 2551.1,1338.9 2564,1326 2564,1214
  Top Layer w10: v1(311,2032) 254,1975 254,313 339,228 1901,228 v1(2410,737) ; v1(326,2255) 341.72,2239.28 524.28,2239.28 566,2281 R5.2@577.78,2281 ; v1(2524,969) 2564,1009 2564,1214
  Bottom Layer w10: v1(311,2032) 333,2054 333,2248 v1(326,2255) ; v1(2410,737) 2410,766 2534,890 2534,959 v1(2524,969)
SDA_C: P4.16 R9.2 U1.28 | length 4462.6
  Top Layer w8: U1.28@2570.79,1380.16 2570.79,1341.21 2582,1330 2582,1214
  Top Layer w10: v1(306,1371) 284,1349 284,331.21 350.21,265 1854,265 2582,993 2582,1214 ; v1(306,1468) 335.28,1497.28 485.28,1497.28 519,1531 R9.2@577.78,1531
  Bottom Layer w10: v1(306,1371) v1(306,1468)
SDA_CTL: JP7.2 U1.56 | length 1348.8
  Top Layer w8: U1.56@2879.84,1748.27 2931.27,1748.27 3415,2232 3704,2232 3776,2304 3776,2385 JP7.2@3876,2485
SDA_D: P5.16 R17.2 U1.29 | length 3889.9
  Top Layer w8: v1(317.14,722.14) 353.28,758.28 P5.16@415.06,758.28 ; U1.29@2590.47,1380.16 2590.47,1346.53 2601,1336 2601,1210
  Top Layer w10: P5.16@415.06,758.28 480.28,758.28 531,809 R17.2@577.78,809 ; v1@2582.5,947.5 2601,966 2601,1210
  Bottom Layer w10: v1(317.14,722.14) 279,684 279,327 346,260 2081,260 2597,776 2597,933 v1(2582,948)
SDA_SINK: P2.16 U1.30 | length 12232.6
  Top Layer w8: U1.30@2610.16,1380.16 2610.16,1347.84 2619,1339 2619,1215
  Top Layer w10: v1(2619,941) 2619,1215 ; v1(4286,2109) 4375.05,2019.95 v1(4375.05,2018.95)
  Bottom Layer w10: v1(2619,941) 2619,476 2249,106 2224.33,106 2223.83,105.5 312.17,105.5 311.67,106 265,106 53,318 53,3204 202,3353 3487,3353 4056,2784 4056,2339 v1(4286,2109) ; v1(4375.05,2018.95) 4541.83,1852.17 P2.16@4739.63,1852.17
SVD: C5.1 C6.1 JP1-1.2 JP1-2.2 U1.31 U1.71 | length 2460.7
  Top Layer w8: U1.31@2630.24,1380.16 2630.24,1353.76 2644,1340 C5.1@2644,1294
  Top Layer w10: v1@2610.16,1849.84 2610.16,1963.16 2646,1999 C6.1@2646,2049 ; v1(2854,2154) 2854,2613 3281,3040 JP1-1.2@3289,3040 ; v1(2880,1185) 2880,1115 2907,1088 3027,1088 JP1-2.2@3100,1015
  Bottom Layer w10: v1(2610.16,1849) 2702.64,1849 2854,2000.36 v1(2854,2154) ; v1(2644,1322) 2780,1186 v1@2880,1186
VDD: C1.1 C2.1 C3.1 C4.1 C9.1 C10.2 JP1-1.1 JP1-2.1 JP2.3 JP3.3 JP4.3 JP5.3 JP6.3 R8.2 R12.2 R13.2 R14.2 R15.2 R20.2 U1.25 U1.50 U1.74 U1.79 U2.2 | length 7033.3
  Top Layer w8: C1.1@2512,1300 C1.1@2512,1300.27
  Top Layer w10: C3.1@2390.68,1965.32 2414.68,1965.32 2452.68,1927.32 2452.68,1858.32 2464,1847 2545,1847 2562,1830 ; C1.1@2511.73,1300.27 2511.73,1414.73 2531,1434 ; 2536,1847 2551.1,1862.1 2551.1,2008.1 C4.1@2559,2016 ; 2831.84,1630.16 3020.16,1630.16 C2.1@3035,1645
  Top Layer w20: 2531,1434 2560,1463 v2(2803,1463) 2821,1481 2821,1845 2834,1858 2872,1858 v1(3285,2271) ; 2562,1830 2577,1815 2821,1815 ; v1(2759.97,2940.03) R20.2@2759.97,2997.73 ; 2821,1630 2832,1630 2831.84,1630.16 ; v2(2877,1389) 2877,1279 2838,1240 2838,1108 2886,1060 2984,1060 3014,1030 3014,947 3046,915 JP1-2.1@3100,915 ; R8.2@2995.03,2619.27 2997.03,2617.27 R14.2@3346.03,2617.27 3360,2631.24 3360,3092 3312,3140 JP1-1.1@3289,3140 ; R15.2@3278.03,717.27 3302.76,742 3431,742 3469,704 ; JP5.3@3672,1088 3760,1000 C9.1@3760,604
  Top Layer w38: JP1-2.1@3100,915 3265,915 3469,711 3469,682 3547,604 C9.1@3760,604
  Bottom Layer w20: JP2.3@2583,2940 3061,2940 3261,3140 JP1-1.1@3289,3140 ; v2(2803,1463) v2(2877,1389) ; v1(3285,2271) v1(3285,2618) ; JP5.3@3673,1089 JP3.3@3866,1089
VSEL: JP4.2 R20.1 R21.1 U1.67 | length 1370.5
  Top Layer w8: U1.67@2688.9,1899.84 2688.9,1931.9 2801,2044 2801,2975 JP4.2@2865,3039 2707.92,3039 R21.1@2706.97,3039.95
WP_SET: JP6.2 U1.66 | length 1285.5
  Top Layer w8: U1.66@2708.58,1899.84 2708.58,1932.58 2827,2051 2827,2804 JP6.2@3062,3039
pads on no net: ?. J1.2 J1.3 J1.4 J1.10 J1.11 P1.14 P2.14 P3.14 P4.14 P5.14

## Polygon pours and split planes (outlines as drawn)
GND on Top Layer "bottom Layer-No Net" (solid, remove dead copper, pour order 1003): 457.07,2584.93 457.07,2575.07 394,2512 394,2466 429,2431 476.07,2383.93 658.07,2383.93 457.07,2584.93
GND on Top Layer "bottom Layer-No Net" (solid, remove dead copper, pour order 1002): 454.07,1842.93 454.07,1834.07 396,1776 396,1725 438,1683 474.07,1646.93 650.07,1646.93 454.07,1842.93
GND on Top Layer "bottom Layer-No Net" (solid, remove dead copper, pour order 1001): 455,1113 455,1100.15 403.93,1049.07 403.93,998.07 444.93,957.07 486,916 652,916 455,1113
GND on Top Layer "bottom Layer-No Net" (solid, remove dead copper, pour order 1000): 819.07,3139.93 665.07,2985.93 665.07,2918.93 461.85,2918.93 457.07,2914.15 457.07,2584.93 639.07,2402.93 658.07,2383.93 658.07,2208.93 629.29,2180.15 466.29,2180.15 454.07,2180.15 454.07,1842.93 650.07,1646.93 650.07,1461.93 628.07,1439.93 626.29,1438.15 454.07,1438.15 454.07,1104.93 651.07,907.93 651.07,743.93 621.07,713.93 606.29,699.15 452.07,699.15 452.07,279.93 1766.07,279.93 2514.07,1027.93 2552.07,1065.93 3057.07,1065.93 3190.07,1198.93 4440.07,1198.93 4686.07,1444.93 4686.07,1971.93 4446.07,2211.93 2871.07,2211.93 2871.07,2457.93 2189.07,3139.93 819.07,3139.93
+5V on Top Layer "bottom Layer-No Net" (solid, remove dead copper, pour order 1000): 2882,530 2882,589 2883,590 3391,590 3415,566 3415,508 2882,508 2882,530
GND on Bottom Layer "bottom Layer-No Net" (solid, remove dead copper, pour order 1004): -3,3340.67 97,3440.67 194,3440.67 3919,3440.67 4319,3040.67 4319,2390.67 4504,2205.67 4688,2021.67 4688,1481.67 4688,1445.67 4320,1077.67 4320,445.67 3874,-0.33 120,-0.33 100,-0.33 -2,101.67 -3,102.67 -3,3340.67

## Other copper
Top Layer:
  rectangle net GND: 2415,1486 2800,1788
  pour cut-out: 2404,1937 2901,1937 2909,1929 2909,1429 2827,1347 2819.2,1354.8 2418.07,1354.8 2418.07,1356.93 2328,1447 2328,1861
  text "TOP LAYER" at 6617,171 h80
  text "1" at 7267,41 h80
Bottom Layer:
  text "BOTTOM LAYER" at 6617,171 h80
  text "4" at 7267,41 h80

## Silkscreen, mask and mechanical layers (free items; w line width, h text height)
Top Overlay:
  rectangle: 3260,60 3920,250
  text "PI3HDMI2410FFE HDMI Switch 2 layer EVB" at 720,3210 h80
  text "REV.A" at 720,3130 h80
  text "VDD" at 3370,3120 h60
  text "GND" at 2400,3110 h60
  text "WP_SET" at 3140,3050 h60 r270
  text "VSEL" at 2930,3040 h60 r270
  text "OE#" at 2400,3020 h60
  text "SVD" at 3370,3000 h60
  text "VDD" at 2400,2910 h60
  text "SDA_CTL" at 3950,2470 h60
  text "SCL_CTL" at 3950,2300 h60
  text "A0" at 3800,1230 h60 r270
  text "A1" at 3620,1220 h60 r270
  text "VDD" at 3940,1070 h60
  text "SVD" at 3185,1000 h60
  text "VDD" at 3189,883 h60
  text "GND" at 3930,860 h60
  text "TOP SILKSCREEN LAYER" at 6617,171 h80
  text "S/N:" at 3110,130 h80
  text "5" at 7267,41 h80
Bottom Overlay:
  text "BOTTOM SILKSCREEN LAYER" at 6617,171 h80
  text "6" at 7267,41 h80
  text "1005DB067" at 3750,40 h60
Top Paste:
  text "TOP PASTE LAYER" at 6617,171 h80
  text "TOP PASTE LAYER" at 6617,171 h80
  text "TP" at 7247,41 h80
Bottom Paste:
  text "BOTTOM PASTE LAYER" at 6617,171 h80
  text "BOTTOM PASTE LAYER" at 6617,171 h80
  text "BP" at 7247,41 h80
Top Solder:
  text "TOP SOLDER LAYER" at 6617,171 h80
  text "7" at 7267,41 h80
Bottom Solder:
  text "BOTTOM SOLDER LAYER" at 6617,171 h80
  text "8" at 7267,41 h80
Drill Guide:
  text "DRILL GUIDE LAYER" at 6617,171 h80
  text "10" at 7247,41 h80
Mechanical 1:
  lines w8: -2,99 ccw(c98,99) 98,-1 3875,-1 4320,444 4320,1077 4505,1262 4838,1262 4916,1340 4916,1456 4819,1456 4819,2012 4917,2012 4917,2127 4838,2206 4503,2206 4320,2389 4320,3041 3921,3440 98,3440 ccw(c97.5,3340.5) -2,3340 -2,99
  lines w10: 6587,131 6587,521 ; 6987,1 6987,131 ; 6987,261 6987,391 ; 7517,261 7517,391
  lines w12: 6067,131 8447,131 ; 6067,261 8447,261 ; 6067,391 8447,391 ; 6067,521 8447,521 ; 6067,581 6517,581 ; 6067,631 6427,631 ; 6067,681 6517,681 ; 7607,581 8382,581 ; 7607,681 8392,681 ; 7697,631 8317,631
  lines w15: 6067,1 8447,1 8447,751 6067,751 6067,1
  text "Pericom" at 6747,581 h180
  text "PCB NAME" at 6107,431 h60
  text "PI3HDMI2410FFE HDMI Switch 2 layer EVB" at 6617,431 h80
  text "REV.A" at 8167,431 h80
  text "DATE" at 6197,301 h60
  text "1/27/2010" at 6607,301 h80
  text "Drawn by" at 7017,301 h60
  text "Haojie Ci" at 7627,301 h80
  text "TITLE" at 6177,171 h60
  text "SHEET NUMBER" at 6187,41 h60
  text "OF       10" at 7487,41 h80
Drill Drawing:
  lines w10: 6534,1498 6534,1988 ; 6604,868 6814,868 ; 6604,1208 6814,1208 ; 6684,928 6704,868 ; 6684,1148 6704,1208 ; 6704,978 6704,868 ; 6704,1098 6704,1208 ; 6724,928 6704,868 ; 6724,1148 6704,1208 ; 6924,1498 6924,1988 ; 7834,1498 7834,1988 ; 8964,1498 8964,1988 ; 6904,868 6904,918 7944,918 7944,868 6904,868 ; 6904,1158 7944,1158 7944,1208 6904,1208 6904,1158
  lines w12: 6044,1628 9564,1628 ; 6044,1758 9564,1758
  lines w15: 6044,1498 6044,1988 9564,1988 9564,1498 6044,1498
  text "IMPEDANCE CHART" at 6044,2018 h100
  text "TRACE" at 6594,1878 h60
  text "SINGLE-ENDED" at 6944,1878 h60
  text "DIFFERENTIAL-ENDED" at 7884,1878 h60
  text "LAYER(S)" at 6084,1838 h60
  text "TOLERANCE" at 9004,1838 h60
  text "TYPE" at 6594,1798 h60
  text "IMPEDANCE REQ'D" at 6944,1798 h60
  text "IMPEDANCE REQ'D" at 7884,1798 h60
  text "+/- 10%" at 9144,1678 h80
  text "1" at 6274,1668 h80
  text "--" at 6719,1668 h80
  text "--" at 7324,1668 h80
  text "--" at 8364,1668 h80
  text "12/8/12mil" at 6581,1539 h80
  text "1" at 6274,1538 h80
  text "--" at 7324,1538 h80
  text "100ohm" at 8264,1538 h80
  text "+/- 10%" at 9144,1538 h80
  text "LAYER1 SIGNAL" at 7984,1158 h80
  text "THICKNESS is 1.6mm" at 6084,1018 h80
  text "LAYER4 SIGNAL" at 7984,868 h80
  text "DRILL DRAWING LAYER" at 6617,171 h80
  text "9" at 7267,41 h80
